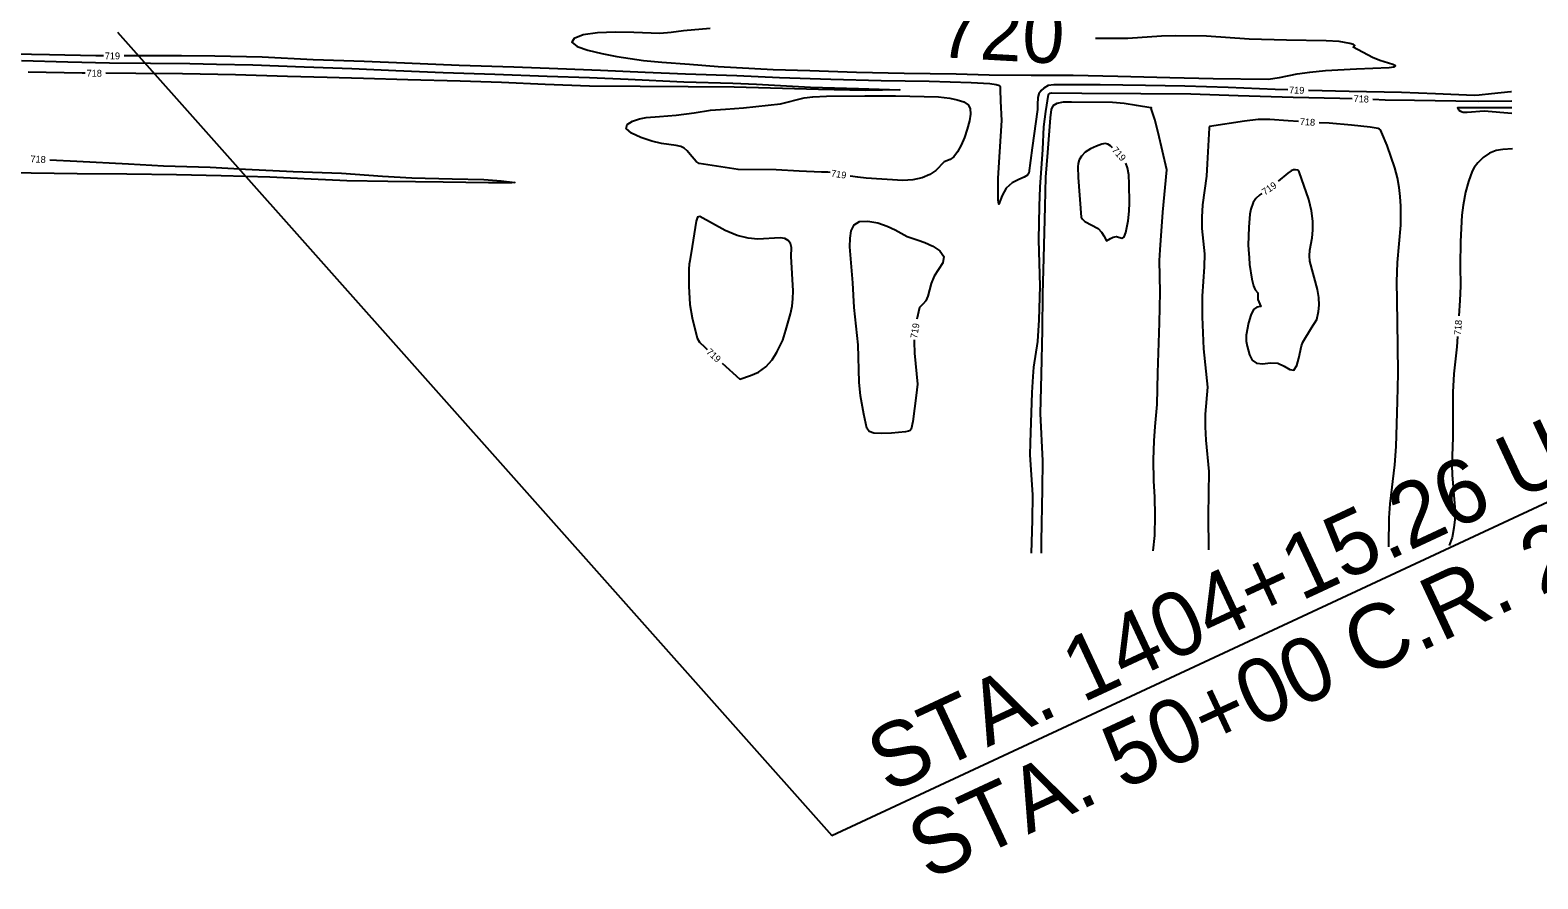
# Model space of a CAD drawing. Extents: x -310467766 to 17062430, y -322263100 to 8322522.
# Drawn here: x 1398585 to 1399466, y 573386 to 573882 of the extents above; entities that cross this region are included whole.
import ezdxf

# ---------------------------------------------------------------- set-up
doc = ezdxf.new("R2010")
doc.units = 0
for name, color, linetype in [('DT_X_Contour_Minor', 7, 'Continuous'), ('Level 19', 7, 'Continuous'), ('Level 40', 7, 'Continuous')]:
    doc.layers.add(name, color=color, linetype=linetype)

msp = doc.modelspace()

# ---------------------------------------------------------------- linework, layer by layer
at = {"layer": 'DT_X_Contour_Minor'}
for points in [[(1398982.78, 573882.87), (1398967.1, 573881.53), (1398959.89, 573880.52), (1398953.32, 573879.95), (1398938.13, 573880.66), (1398927.46, 573880.86), (1398916.91, 573880.45), (1398908.53, 573879.16), (1398903.3, 573877.18), (1398901.98, 573874.87), (1398904.95, 573872.51), (1398911.22, 573870.27), (1398919.42, 573868.26), (1398928.25, 573866.58), (1398943.73, 573864.31), (1398954.6, 573863.19), (1398970.61, 573862), (1398987.44, 573860.72), (1399019.62, 573859), (1399041.09, 573858.3), (1399068.21, 573857.47), (1399096.12, 573856.79), (1399126.52, 573856.43), (1399145.81, 573855.79), (1399170.39, 573855.71), (1399194.84, 573855.74), (1399220.94, 573855.15), (1399251.41, 573854.32), (1399276.63, 573853.72), (1399308.74, 573853.37), (1399315.36, 573854.29), (1399325.73, 573856.34), (1399333.19, 573857.42), (1399342.3, 573858.29), (1399360.44, 573859.31), (1399379.47, 573860.05), (1399382.24, 573860.56), (1399383.17, 573861.18), (1399381.66, 573861.88), (1399374.07, 573864.17), (1399369.72, 573866.02), (1399358.51, 573871.96), (1399359.45, 573872.99), (1399358.65, 573873.53), (1399356.63, 573874.19), (1399350.4, 573875.36), (1399342.69, 573875.8), (1399319.62, 573876.18), (1399297.65, 573876.79), (1399272.74, 573878.44), (1399254.82, 573878.73), (1399246.57, 573878.51), (1399226.8, 573877.1), (1399207.87, 573877.18)], [(1398628.27, 573866.92), (1398623.87, 573866.92), (1398596.79, 573867.61), (1398575.77, 573867.98)], [(1398580.36, 573864.17), (1398607.44, 573863.5), (1398631.76, 573862.9), (1398655.69, 573862.59), (1398678.74, 573862.45), (1398694.32, 573862.18), (1398715.56, 573861.62), (1398745.55, 573860.45), (1398773.32, 573859.48), (1398799.13, 573858.31), (1398826.79, 573857.31), (1398857.02, 573856.24), (1398887.49, 573855.16), (1398912.27, 573854.33), (1398934.9, 573853.41), (1398967.3, 573851.77), (1398996.03, 573850.89), (1399009.77, 573850.3), (1399041.34, 573848.59), (1399069.51, 573847.83), (1399093.55, 573847.02), (1399073.54, 573846.69), (1399046.09, 573847.27), (1399018.08, 573848), (1398996.82, 573848.55), (1398969.88, 573848.74), (1398941.78, 573848.94), (1398912.3, 573849.25), (1398886.28, 573850.11), (1398860.82, 573851.33), (1398836.69, 573852.07), (1398806.05, 573852.84), (1398780.29, 573853.77), (1398758.88, 573854.3), (1398735.72, 573854.88), (1398705.48, 573855.81), (1398674.39, 573856.46), (1398647.22, 573856.64), (1398629.63, 573856.75)], [(1399320.31, 573847.01), (1399312.96, 573847.21), (1399285.51, 573848.47), (1399260.09, 573849.28), (1399237.09, 573849.65), (1399210.57, 573849.97), (1399183.67, 573849.92), (1399180.19, 573849.67), (1399177.83, 573848.1), (1399176.17, 573846.62), (1399174.81, 573844.75), (1399174.15, 573842.57), (1399174.06, 573838.52), (1399173.95, 573835.65), (1399170.91, 573813.21), (1399168.9, 573798.32), (1399168.17, 573797.22), (1399166.33, 573795.99), (1399163.11, 573794.59), (1399159.25, 573792.61), (1399155.77, 573789.54), (1399153.44, 573785.3), (1399151.46, 573780.17), (1399151.12, 573782.65), (1399150.98, 573795.26), (1399151.37, 573801.73), (1399153.15, 573829.12), (1399152.6, 573840.44), (1399152.39, 573847.26), (1399152.46, 573848.56), (1399151.8, 573849.35), (1399149.88, 573850.06), (1399146.25, 573850.56), (1399135.34, 573851.14), (1399110.76, 573851.87), (1399082.68, 573852.29), (1399053.3, 573853.09), (1399023.19, 573854.18), (1398998.33, 573855.32), (1398968.37, 573856.26), (1398944.76, 573857.14), (1398918.59, 573858.39), (1398893.83, 573859.35), (1398868.05, 573860.32), (1398836.01, 573861.38), (1398804.22, 573862.68), (1398780.67, 573863.57), (1398750.79, 573864.6), (1398720.94, 573866.17), (1398693.3, 573866.81), (1398673.91, 573867), (1398647.81, 573866.93), (1398640.27, 573866.93)], [(1398617.63, 573856.82), (1398615.85, 573856.83), (1398584.16, 573857.5)], [(1399052.79, 573798.75), (1399051.48, 573799.01), (1399047.88, 573799), (1399034.85, 573799.6), (1399021.3, 573800.24), (1398999.22, 573800.46), (1398976.26, 573804.04), (1398974.65, 573805.1), (1398971.16, 573809.36), (1398969.37, 573811.51), (1398967.63, 573812.98), (1398965.62, 573813.89), (1398962.92, 573814.48), (1398954.41, 573815.79), (1398948.67, 573817.14), (1398942.3, 573819.25), (1398936.74, 573821.83), (1398933.66, 573824.46), (1398934.21, 573826.79), (1398937.34, 573828.68), (1398941.48, 573830.06), (1398945.38, 573830.87), (1398953.19, 573831.57), (1398962.98, 573832.26), (1398973.45, 573833.7), (1398983.04, 573835.26), (1398991.72, 573835.79), (1399002.2, 573836.55), (1399023.86, 573838.88), (1399037.75, 573842.35), (1399042.68, 573842.99), (1399050.71, 573843.31), (1399073.2, 573843.49), (1399091.12, 573843.59), (1399116.28, 573843.03), (1399122.72, 573842.18), (1399127.09, 573841.31), (1399130.93, 573840.08), (1399133.45, 573838.39), (1399134.68, 573836.08), (1399134.87, 573832.94), (1399134.26, 573828.86), (1399133.02, 573824.17), (1399131.34, 573819.3), (1399129.38, 573814.69), (1399127.27, 573810.76), (1399125.12, 573807.93), (1399123.04, 573806.43), (1399119.57, 573804.99), (1399114.65, 573799.82), (1399111.18, 573797.61), (1399106.62, 573795.69), (1399101.27, 573794.45), (1399095.44, 573794.14), (1399073.96, 573795.53), (1399068.96, 573795.97), (1399064.61, 573796.66)], [(1399170.55, 573576.17), (1399171.19, 573595.53), (1399171.36, 573610.25), (1399169.8, 573633.61), (1399169.87, 573640.67), (1399170.92, 573670.15), (1399171.43, 573679.51), (1399171.95, 573684.9), (1399174.26, 573699.92), (1399174.99, 573712.55), (1399175.64, 573732.3), (1399174.76, 573759.46), (1399175.14, 573779.02), (1399175.61, 573790.16), (1399177.16, 573812.23), (1399177.77, 573825.44), (1399178.87, 573834.37), (1399180.5, 573844.45), (1399181.53, 573845.23), (1399182.43, 573845.3), (1399200.02, 573845.21), (1399234.43, 573844.9), (1399263.65, 573844.68), (1399291.2, 573843.79), (1399323.44, 573842.71), (1399350.62, 573842.21), (1399357.98, 573841.96)], [(1399451.04, 573845.93), (1399450.62, 573845.91), (1399439.24, 573844.77), (1399432.1, 573843.91), (1399429.12, 573843.86), (1399406.6, 573844.84), (1399386.75, 573845.6), (1399356.24, 573846.19), (1399332.31, 573846.71)], [(1399241.55, 573577.46), (1399242.53, 573586.51), (1399242.88, 573598.19), (1399242.53, 573608.87), (1399241.93, 573618.54), (1399241.81, 573630.71), (1399242.11, 573641.84), (1399242.71, 573650.23), (1399243.92, 573663.12), (1399244.39, 573681.66), (1399245.39, 573710.84), (1399245.68, 573728.7), (1399245.41, 573747.24), (1399245.7, 573753.47), (1399247.35, 573775.63), (1399249.56, 573800.34), (1399244.58, 573822.21), (1399242.5, 573829.82), (1399240.54, 573836.24), (1399240.56, 573836.5), (1399240.21, 573836.65), (1399231.83, 573837.92), (1399224.59, 573839.11), (1399217.79, 573839.65), (1399193.81, 573839.88), (1399188.96, 573839.8), (1399185.25, 573839.16), (1399183.07, 573837.73), (1399182.07, 573835.68), (1399181.5, 573830.75), (1399179.89, 573810.43), (1399178.8, 573796.09), (1399178.3, 573778.96), (1399177.59, 573748.62), (1399177.04, 573727.71), (1399176.75, 573706.82), (1399176.18, 573680.65), (1399175.68, 573657.87), (1399176.92, 573630.25), (1399176.78, 573613.75), (1399176.27, 573582.91), (1399176.09, 573576.27)], [(1399369.97, 573841.56), (1399377.27, 573841.31), (1399394.32, 573841), (1399418.54, 573840.73), (1399431.76, 573840.42), (1399451.13, 573840.67)], [(1399451.2, 573836.54), (1399439.56, 573836.59), (1399419.4, 573836.55), (1399420.19, 573835.29), (1399421.11, 573834.54), (1399422.74, 573834.04), (1399425.19, 573834.02), (1399435.04, 573834.84), (1399451.26, 573833.36)], [(1399326.6, 573828.59), (1399320.53, 573828.96), (1399309.84, 573829.8), (1399302.94, 573829.66), (1399295.07, 573828.84), (1399274.49, 573825.59), (1399274.35, 573824.87), (1399273.27, 573803.82), (1399272.79, 573796.56), (1399270.48, 573779.89), (1399269.98, 573772.68), (1399270.14, 573765.96), (1399271.61, 573751.19), (1399271.35, 573743.65), (1399270.3, 573726.45), (1399270.33, 573714.45), (1399271.03, 573695.59), (1399273.32, 573673.14), (1399272.05, 573657.54), (1399271.92, 573649.95), (1399272.34, 573642.22), (1399274.22, 573623.95), (1399273.81, 573598.14), (1399273.96, 573578.05)], [(1399379.35, 573579.97), (1399379.34, 573580.58), (1399379.47, 573596.74), (1399380.17, 573605), (1399382.9, 573627.77), (1399383.53, 573638.5), (1399384.3, 573664.82), (1399384.75, 573681.26), (1399384.57, 573697.47), (1399384.23, 573724.13), (1399383.91, 573734.76), (1399384.46, 573746.21), (1399386.4, 573768.04), (1399386.38, 573779.14), (1399386.01, 573784.65), (1399385.37, 573790.03), (1399384.34, 573795.54), (1399382.77, 573801.53), (1399378.3, 573814.46), (1399375.11, 573822.37), (1399374.4, 573823.66), (1399373.86, 573824.12), (1399373.07, 573824.43), (1399368.46, 573825.24), (1399357.54, 573826.48), (1399344.37, 573827.51), (1399338.58, 573827.86)], [(1399217.83, 573813.19), (1399216.66, 573814.27), (1399215.08, 573815.4), (1399213.65, 573815.7), (1399211.63, 573815.25), (1399208.55, 573814.15), (1399205.01, 573812.53), (1399201.83, 573810.55), (1399199.69, 573808.35), (1399198.47, 573806.11), (1399197.87, 573804), (1399197.64, 573802.04), (1399197.89, 573795.86), (1399199.59, 573772.68), (1399200.24, 573771.4), (1399201.65, 573770.1), (1399209.5, 573765.92), (1399211.52, 573763.87), (1399212.88, 573761.75), (1399214.32, 573758.71), (1399216.63, 573760.2), (1399218.33, 573760.98), (1399220.14, 573761.24), (1399223.34, 573760.34), (1399224.62, 573761.07), (1399225.65, 573763.63), (1399226.96, 573770.58), (1399227.56, 573776.05), (1399227.71, 573780.99), (1399227.66, 573791.93), (1399227.35, 573797.42), (1399226.7, 573801.51), (1399225.73, 573804.15)], [(1399451.63, 573812.59), (1399445.94, 573812.22), (1399441.99, 573811.61), (1399438.14, 573810.14), (1399434.52, 573807.56), (1399431.41, 573804.45), (1399429.15, 573801.6), (1399427.93, 573799.62), (1399425.81, 573793.48), (1399424.1, 573787.2), (1399422.69, 573779.72), (1399422.07, 573773.74), (1399421.25, 573758.33), (1399421.1, 573744.43), (1399421.26, 573732.31), (1399420.86, 573723.97), (1399420.24, 573714.86)], [(1398596.84, 573806.17), (1398612.62, 573805.38), (1398642.86, 573803.73), (1398663.35, 573802.61), (1398690.66, 573801.78), (1398711.32, 573800.76), (1398739.14, 573799.25), (1398767.35, 573798.44), (1398791.32, 573796.69), (1398808.4, 573795.61), (1398832.01, 573795.11), (1398850.49, 573794.65), (1398860.66, 573793.87), (1398868.56, 573792.86), (1398866.87, 573792.63), (1398853.24, 573792.64), (1398826.84, 573793.13), (1398794.32, 573793.57), (1398770.44, 573793.89), (1398749.54, 573794.84), (1398725.45, 573795.94), (1398697.03, 573796.71), (1398670.83, 573797.35), (1398641.95, 573797.74), (1398612.86, 573798.01), (1398585.99, 573798.42), (1398565.84, 573798.96)], [(1399305.19, 573786.44), (1399303.99, 573785.61), (1399301.55, 573783.48), (1399300.03, 573781.24), (1399298.78, 573777.33), (1399298.15, 573774.46), (1399297.54, 573766.82), (1399297.18, 573756.27), (1399297.47, 573751.2), (1399297.7, 573749.1), (1399297.99, 573744.96), (1399299.26, 573736.41), (1399300.22, 573732.55), (1399301.29, 573730.24), (1399302.81, 573728.31), (1399302.81, 573724.58), (1399304.48, 573720.36), (1399302.13, 573720.1), (1399300.32, 573718.71), (1399298.66, 573715.35), (1399297.31, 573710.9), (1399295.93, 573703.61), (1399295.94, 573700.16), (1399296.47, 573697.27), (1399297.92, 573692.07), (1399299.46, 573689.11), (1399301.98, 573687.2), (1399305.66, 573686.97), (1399310, 573687.43), (1399314.37, 573687.2), (1399318.22, 573685.45), (1399321.4, 573683.49), (1399323.85, 573683.19), (1399325.58, 573685.81), (1399326.75, 573690.16), (1399328.25, 573697.39), (1399329.09, 573699.47), (1399334.22, 573707.96), (1399337.21, 573712.8), (1399338.14, 573717.49), (1399338.54, 573721.18), (1399338.44, 573725.58), (1399337.58, 573730.37), (1399333.1, 573746.88), (1399332.91, 573750.07), (1399333.21, 573753.28), (1399334.45, 573760.62), (1399334.94, 573765.11), (1399334.95, 573770.3), (1399334.19, 573776.26), (1399332.49, 573782.87), (1399326.93, 573799.08), (1399326.16, 573800.07), (1399324.73, 573800.32), (1399323.7, 573800.21), (1399322.27, 573799.65), (1399320.24, 573798.31), (1399314.75, 573793.7)], [(1398989.84, 573687.24), (1399000.01, 573677.99), (1399006.41, 573680.03), (1399010.91, 573682.03), (1399015.38, 573685.09), (1399019.02, 573689.23), (1399021.72, 573693.62), (1399025.14, 573700.81), (1399027.01, 573706.54), (1399029.71, 573716.04), (1399030.65, 573720.5), (1399031.15, 573724.86), (1399031.2, 573729.61), (1399030.09, 573749.62), (1399030.31, 573754.98), (1399029.71, 573757.18), (1399028.42, 573759.01), (1399026.4, 573760.21), (1399023.59, 573760.62), (1399010.69, 573759.86), (1399004.95, 573760.26), (1398998.49, 573761.86), (1398991.48, 573764.91), (1398976.66, 573773.1), (1398975.29, 573772.69), (1398974.58, 573770.21), (1398972.16, 573755.45), (1398970.84, 573747.03), (1398970.49, 573745.17), (1398970.25, 573742.13), (1398970.29, 573732.3), (1398970.83, 573721.5), (1398972.32, 573713.71), (1398975.16, 573701.81), (1398976.54, 573699.63), (1398979.55, 573696.59), (1398980.97, 573695.31)], [(1399102, 573701), (1399101.9, 573699.82), (1399102.1, 573693.08), (1399103.82, 573675.07), (1399103.23, 573668.39), (1399101.23, 573653.18), (1399100.2, 573648.67), (1399099.6, 573647.94), (1399098.66, 573647.45), (1399096.87, 573647.03), (1399088.68, 573646.25), (1399083.14, 573646.07), (1399078.45, 573646.31), (1399075.67, 573647.23), (1399074.32, 573649.17), (1399072.56, 573657.4), (1399070.65, 573668.26), (1399069.88, 573676.15), (1399069.21, 573698.01), (1399066.82, 573719.73), (1399066.16, 573734.28), (1399064.41, 573755.35), (1399064.5, 573760.26), (1399065.17, 573764.65), (1399066.85, 573768.09), (1399070.02, 573770.09), (1399074.89, 573770.35), (1399080.66, 573769.24), (1399086.27, 573767.33), (1399090.89, 573765.13), (1399097.88, 573761.28), (1399104.26, 573759.17), (1399108.19, 573757.83), (1399112.81, 573755.72), (1399116.99, 573752.9), (1399119.24, 573749.61), (1399118.64, 573746.01), (1399113.56, 573738.12), (1399111.87, 573733.91), (1399109.97, 573726.38), (1399108.7, 573723.73), (1399107.27, 573721.88), (1399105.15, 573719.86), (1399103.58, 573712.91)], [(1399419.42, 573702.89), (1399419.02, 573696.89), (1399417.24, 573681), (1399416.82, 573670.3), (1399416.65, 573643.8), (1399416.14, 573627.66), (1399416.29, 573621.99), (1399418.03, 573600.58), (1399417.86, 573595.89), (1399417.37, 573590.9), (1399416.39, 573585.28), (1399414.57, 573580.61)]]:
    msp.add_lwpolyline(points, dxfattribs=at)
at = {"layer": 'Level 40'}
for p, q in [((1398636.47, 573880.82), (1399053.94, 573411.13)), ((1399053.94, 573411.13), (1399774.57, 573747.17))]:
    msp.add_line(p, q, dxfattribs=at)

# ---------------------------------------------------------------- texts
at = {"layer": 'Level 19'}
for s, height, rotation, p in [('720', 33, 356.84958, (1399115.36, 573866.27)), ('719', 4, 0.04584, (1398629.01, 573864.92)), ('718', 4, 359.65707, (1398618.38, 573854.81)), ('719', 4, 358.49969, (1399321, 573845)), ('718', 4, 358.05279, (1399358.67, 573839.94)), ('718', 4, 356.5058, (1399327.23, 573826.55)), ('718', 4, 357.13032, (1398585.51, 573804.73)), ('719', 4, 311.68331, (1399217.19, 573811.62)), ('719', 4, 350.97103, (1399053.18, 573796.45)), ('719', 4, 34.92751, (1399306.94, 573785.23)), ('719', 4, 80.38025, (1399103.64, 573701.48)), ('718', 4, 86.11556, (1399421.47, 573703.51)), ('719', 4, 317.71083, (1398980.17, 573693.33))]:
    msp.add_text(s, height=height, rotation=rotation, dxfattribs=at).set_placement(p)
at = {"layer": 'Level 40'}
for s, p in [('STA. 1404+15.26 U.S. 24 =', (1399086.59, 573435.39)), ('STA. 50+00 C.R. 224', (1399110.36, 573384.41))]:
    msp.add_text(s, height=37.5, rotation=25, dxfattribs=at).set_placement(p)

doc.saveas('drawing.dxf')
